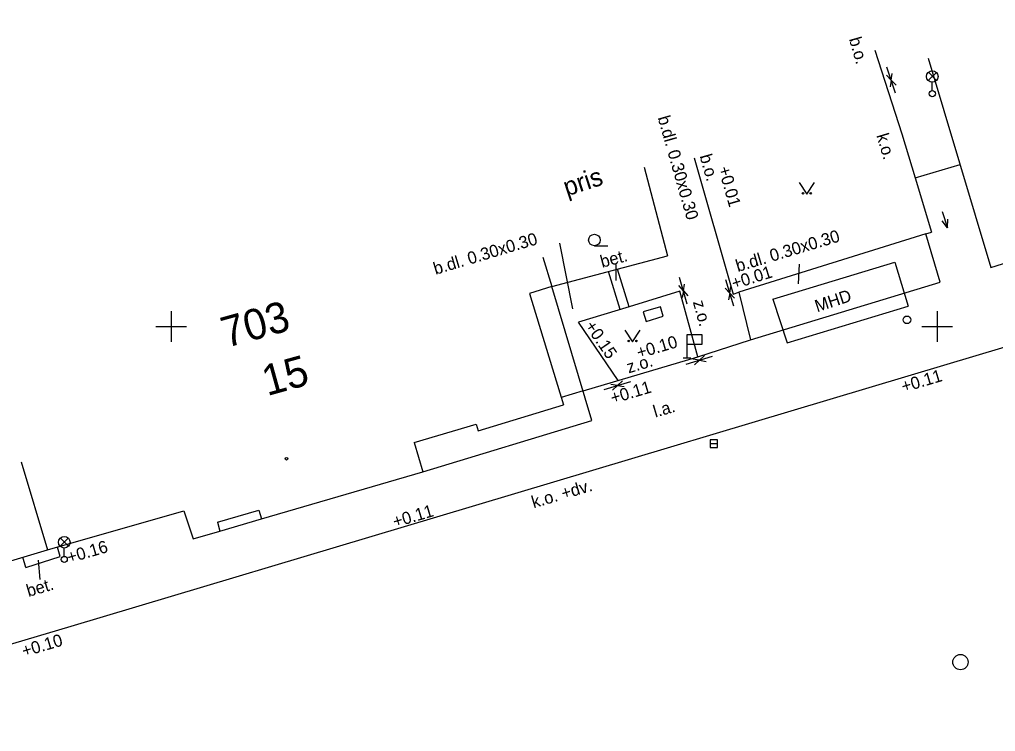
# Model space of a CAD drawing. Extents: x -597333 to -596488, y -1158921 to -1158644.
# Drawn here: x -596804.95 to -596773.1, y -1158738.21 to -1158714.98 of the extents above; entities that cross this region are included whole.
import ezdxf

# ---------------------------------------------------------------- set-up
doc = ezdxf.new("R2010")
doc.units = 0
for name, color, linetype in [('Vrstva 10', 7, 'Continuous'), ('Vrstva 12', 7, 'Continuous'), ('Vrstva 14', 7, 'Continuous'), ('Vrstva 15', 7, 'Continuous'), ('Vrstva 19', 7, 'Continuous'), ('Vrstva 23', 7, 'Continuous'), ('Vrstva 25', 7, 'Continuous'), ('Vrstva 29', 7, 'Continuous'), ('Vrstva 4', 7, 'Continuous'), ('Vrstva 43', 7, 'Continuous'), ('Vrstva 45', 7, 'Continuous'), ('Vrstva 49', 7, 'Continuous'), ('Vrstva 5', 7, 'Continuous'), ('Vrstva 50', 7, 'Continuous'), ('Vrstva 62', 7, 'Continuous'), ('Vrstva 7', 7, 'Continuous')]:
    doc.layers.add(name, color=color, linetype=linetype)

msp = doc.modelspace()

# ---------------------------------------------------------------- linework, layer by layer
at = {"layer": 'Vrstva 10'}
for p in [(-596784.568, -1158719.796), (-596787.575, -1158723.691)]:
    msp.add_line(p, (-596783.805, -1158722.696), dxfattribs=at)
msp.add_lwpolyline([(-596775.29, -1158716.24), (-596773.25, -1158723.07), (-596768.45, -1158721.56)], dxfattribs=at)
at = {"layer": 'Vrstva 12'}
for p, q in [((-596775.369, -1158721.975), (-596781.47, -1158723.88)), ((-596774.9, -1158723.55), (-596775.369, -1158721.975)), ((-596783.4, -1158723.85), (-596785.058, -1158724.356)), ((-596781.47, -1158723.88), (-596781.09, -1158725.43))]:
    msp.add_line(p, q, dxfattribs=at)
msp.add_lwpolyline([(-596785.058, -1158724.356), (-596786.71, -1158724.86)], dxfattribs=at)
at = {"layer": 'Vrstva 14'}
msp.add_line((-596786.189, -1158722.363), (-596785.751, -1158722.363), dxfattribs=at)
for points in [[(-596779.503, -1158720.299), (-596779.253, -1158720.674), (-596779.003, -1158720.299)], [(-596785.191, -1158725.12), (-596784.941, -1158725.495), (-596784.691, -1158725.12)]]:
    msp.add_lwpolyline(points, dxfattribs=at)
for centre, radius in [((-596779.378, -1158720.649), 0.025), ((-596779.128, -1158720.649), 0.025), ((-596786.189, -1158722.175), 0.188), ((-596785.066, -1158725.47), 0.025), ((-596784.816, -1158725.47), 0.025)]:
    msp.add_circle(centre, radius, dxfattribs=at)
at = {"layer": 'Vrstva 15'}
for p, q in [((-596785.344, -1158724.443), (-596785.723, -1158723.202)), ((-596785.058, -1158724.356), (-596785.434, -1158723.126))]:
    msp.add_line(p, q, dxfattribs=at)
msp.add_circle((-596796.235, -1158729.312), 0.0438, dxfattribs=at)
at = {"layer": 'Vrstva 19'}
for p, q in [((-596783.17, -1158725.57), (-596783.17, -1158726.02)), ((-596783.295, -1158726.02), (-596783.045, -1158726.02))]:
    msp.add_line(p, q, dxfattribs=at)
msp.add_lwpolyline([(-596783.17, -1158725.57), (-596782.67, -1158725.57), (-596782.67, -1158725.27), (-596783.17, -1158725.27)], close=True, dxfattribs=at)
at = {"layer": 'Vrstva 23'}
msp.add_circle((-596775.99, -1158724.78), 0.125, dxfattribs=at)
at = {"layer": 'Vrstva 25'}
msp.add_line((-596782.415, -1158728.82), (-596782.165, -1158728.82), dxfattribs=at)
msp.add_lwpolyline([(-596782.415, -1158728.945), (-596782.165, -1158728.945), (-596782.165, -1158728.695), (-596782.415, -1158728.695)], close=True, dxfattribs=at)
msp.add_circle((-596774.24, -1158735.95), 0.25, dxfattribs=at)
at = {"layer": 'Vrstva 29'}
for p, q in [((-596775.292, -1158716.969), (-596775.028, -1158716.705)), ((-596775.024, -1158716.968), (-596775.288, -1158716.703)), ((-596775.16, -1158717.3), (-596775.16, -1158717.025)), ((-596803.622, -1158732.169), (-596803.358, -1158731.905)), ((-596803.354, -1158732.168), (-596803.618, -1158731.903)), ((-596803.49, -1158732.5), (-596803.49, -1158732.225))]:
    msp.add_line(p, q, dxfattribs=at)
msp.add_lwpolyline([(-596784.5, -1158724.83), (-596783.94, -1158724.66), (-596784.033, -1158724.354), (-596784.593, -1158724.524)], close=True, dxfattribs=at)
for centre, radius in [((-596775.16, -1158716.838), 0.188), ((-596775.16, -1158717.4), 0.1), ((-596803.49, -1158732.038), 0.188), ((-596803.49, -1158732.6), 0.1)]:
    msp.add_circle(centre, radius, dxfattribs=at)
at = {"layer": 'Vrstva 4'}
for p, q in [((-596787.867, -1158722.735), (-596787.575, -1158723.691)), ((-596787.575, -1158723.691), (-596788.311, -1158723.916)), ((-596788.311, -1158723.916), (-596787.2, -1158727.55)), ((-596789.98, -1158728.4), (-596787.2, -1158727.55)), ((-596792.071, -1158728.78), (-596791.79, -1158729.74)), ((-596804.9, -1158729.416), (-596804.04, -1158732.29)), ((-596804.04, -1158732.29), (-596799.59, -1158731.01)), ((-596799.59, -1158731.01), (-596799.28, -1158731.93)), ((-596798.408, -1158731.675), (-596797.051, -1158731.278)), ((-596797.135, -1158730.99), (-596797.051, -1158731.278)), ((-596798.492, -1158731.387), (-596798.408, -1158731.675)), ((-596799.28, -1158731.93), (-596798.408, -1158731.675)), ((-596808.152, -1158733.521), (-596804.04, -1158732.29))]:
    msp.add_line(p, q, dxfattribs=at)
for points in [[(-596791.79, -1158729.74), (-596786.27, -1158728.06), (-596787.575, -1158723.691)], [(-596792.071, -1158728.78), (-596790.047, -1158728.18), (-596789.98, -1158728.4)], [(-596797.051, -1158731.279), (-596791.79, -1158729.74)]]:
    msp.add_lwpolyline(points, dxfattribs=at)
at = {"layer": 'Vrstva 45'}
for p, q in [((-596780.36, -1158724.11), (-596776.383, -1158722.902)), ((-596776.383, -1158722.902), (-596775.95, -1158724.33)), ((-596780.36, -1158724.11), (-596779.9, -1158725.53)), ((-596779.9, -1158725.53), (-596775.95, -1158724.33))]:
    msp.add_line(p, q, dxfattribs=at)
at = {"layer": 'Vrstva 49'}
for p, q in [((-596776.361, -1158717.388), (-596776.643, -1158716.532)), ((-596776.502, -1158716.96), (-596776.659, -1158716.8)), ((-596776.502, -1158716.96), (-596776.535, -1158717.179)), ((-596776.502, -1158716.96), (-596776.472, -1158716.739)), ((-596776.502, -1158716.96), (-596776.344, -1158717.118)), ((-596774.838, -1158721.24), (-596774.665, -1158721.776)), ((-596774.665, -1158721.776), (-596774.839, -1158721.554)), ((-596774.665, -1158721.776), (-596774.657, -1158721.493)), ((-596787.332, -1158722.279), (-596786.907, -1158724.418)), ((-596785.493, -1158722.969), (-596785.493, -1158723.5)), ((-596779.507, -1158722.96), (-596779.538, -1158723.609)), ((-596783.164, -1158724.265), (-596783.406, -1158723.397)), ((-596783.285, -1158723.831), (-596783.245, -1158723.611)), ((-596781.64, -1158724.339), (-596781.902, -1158723.477)), ((-596783.285, -1158723.831), (-596783.435, -1158723.664)), ((-596783.285, -1158723.831), (-596783.328, -1158724.048)), ((-596783.285, -1158723.831), (-596783.135, -1158723.996)), ((-596781.771, -1158723.908), (-596781.924, -1158723.744)), ((-596781.771, -1158723.908), (-596781.809, -1158724.126)), ((-596781.771, -1158723.908), (-596781.736, -1158723.688)), ((-596781.771, -1158723.908), (-596781.617, -1158724.07)), ((-596783.193, -1158726.229), (-596782.329, -1158725.971)), ((-596782.761, -1158726.1), (-596782.979, -1158726.061)), ((-596782.761, -1158726.1), (-596782.923, -1158726.253)), ((-596782.761, -1158726.1), (-596782.597, -1158725.947)), ((-596782.761, -1158726.1), (-596782.541, -1158726.136)), ((-596785.865, -1158727.054), (-596785.001, -1158726.796)), ((-596785.433, -1158726.925), (-596785.269, -1158726.772)), ((-596785.433, -1158726.925), (-596785.651, -1158726.886)), ((-596785.433, -1158726.925), (-596785.595, -1158727.078)), ((-596785.433, -1158726.925), (-596785.213, -1158726.961)), ((-596804.275, -1158733.257), (-596804.328, -1158732.626))]:
    msp.add_line(p, q, dxfattribs=at)
at = {"layer": 'Vrstva 5'}
msp.add_line((-596798.492, -1158731.387), (-596797.135, -1158730.99), dxfattribs=at)
at = {"layer": 'Vrstva 62'}
for p, q in [((-596800, -1158724.5), (-596800, -1158725.5)), ((-596775, -1158724.5), (-596775, -1158725.5)), ((-596800.5, -1158725), (-596799.5, -1158725)), ((-596775.5, -1158725), (-596774.5, -1158725))]:
    msp.add_line(p, q, dxfattribs=at)
at = {"layer": 'Vrstva 7'}
for p, q in [((-596782.928, -1158719.498), (-596781.66, -1158723.939)), ((-596775.721, -1158720.147), (-596774.254, -1158719.709)), ((-596775.37, -1158721.973), (-596775.191, -1158721.919)), ((-596782.81, -1158725.99), (-596783.4, -1158723.85)), ((-596781.66, -1158723.939), (-596781.47, -1158723.88)), ((-596785.41, -1158726.76), (-596786.71, -1158724.86)), ((-596786.557, -1158727.1), (-596782.81, -1158725.99)), ((-596786.557, -1158727.1), (-596787.273, -1158727.312)), ((-596803.62, -1158732.5), (-596803.708, -1158732.194)), ((-596804.74, -1158732.86), (-596804.839, -1158732.529)), ((-596804.74, -1158732.86), (-596803.62, -1158732.5))]:
    msp.add_line(p, q, dxfattribs=at)
for points in [[(-596838.86, -1158745.39), (-596830.57, -1158742.87), (-596825.17, -1158741.29), (-596822.55, -1158740.48), (-596812.47, -1158737.51), (-596803.27, -1158734.78), (-596791.33, -1158731.21), (-596774.68, -1158726.23), (-596759.56, -1158721.71), (-596748.14, -1158718.32), (-596736.94, -1158714.98)], [(-596777.04, -1158715.979), (-596776.15, -1158718.71), (-596775.721, -1158720.147), (-596775.191, -1158721.919)], [(-596782.81, -1158725.99), (-596781.09, -1158725.43), (-596774.9, -1158723.55)]]:
    msp.add_lwpolyline(points, dxfattribs=at)

# ---------------------------------------------------------------- texts
at = {"layer": 'Vrstva 43'}
for s, p in [('703', (-596798.204, -1158725.698)), ('15', (-596796.869, -1158727.272))]:
    msp.add_text(s, height=1, rotation=15.5254, dxfattribs=at).set_placement(p)
at = {"layer": 'Vrstva 49'}
for s, height, rotation, p in [('b.o.', 0.4, 285.9352, (-596777.882, -1158715.613)), ('b.dl. 0.30x0.30', 0.4, 285.9352, (-596784.126, -1158718.18)), ('k.o.', 0.4, 286.6224, (-596776.989, -1158718.76)), ('b.o.', 0.4, 285.9352, (-596782.758, -1158719.433)), ('pris', 0.6, 18.0429, (-596787.089, -1158720.755)), ('b.dl. 0.30x0.30', 0.4, 16.6724, (-596791.374, -1158723.312)), ('b.dl. 0.30x0.30', 0.4, 16.6724, (-596781.508, -1158723.221)), ('bet.', 0.4, 14.7847, (-596785.937, -1158723.083)), ('MHD', 0.4, 18.1365, (-596778.919, -1158724.535)), ('z.o.', 0.4, 285.4136, (-596782.978, -1158724.198)), ('z.o.', 0.4, 16.5012, (-596785.07, -1158726.529)), ('l.a.', 0.4, 16.5505, (-596784.201, -1158727.974)), ('k.o. +dv.', 0.4, 16.569, (-596788.172, -1158730.932)), ('bet.', 0.4, 16.345, (-596804.657, -1158733.825))]:
    msp.add_text(s, height=height, rotation=rotation, dxfattribs=at).set_placement(p)
at = {"layer": 'Vrstva 50'}
for s, rotation, p in [('+0.01', 285.9352, (-596782.152, -1158719.832)), ('+0.01', 17.3407, (-596781.638, -1158723.788)), ('+0.15', 304.3803, (-596786.515, -1158724.977)), ('+0.10', 16.4969, (-596784.739, -1158726.049)), ('+0.11', 16.5375, (-596776.101, -1158727.155)), ('+0.11', 16.4969, (-596785.594, -1158727.527)), ('+0.11', 16.5375, (-596792.701, -1158731.566)), ('+0.16', 16.345, (-596803.331, -1158732.731)), ('+0.10', 16.5375, (-596804.806, -1158735.786))]:
    msp.add_text(s, height=0.4, rotation=rotation, dxfattribs=at).set_placement(p)

doc.saveas('drawing.dxf')
